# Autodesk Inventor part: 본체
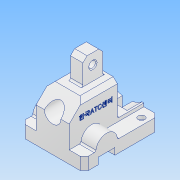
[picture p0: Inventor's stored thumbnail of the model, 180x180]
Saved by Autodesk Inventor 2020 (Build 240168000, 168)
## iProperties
Created: 2022-08
Part Number: 본체
Material: 알루미늄 6061
Document SubType Name: Modeling
Designer: user
Density: 2.7 g/cm^3
Appearance: 알루미늄 - 평지
Mass: 498.899 g
Surface Area: 338.01 cm^2
Volume: 184.777 cm^3
Author: user
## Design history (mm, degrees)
sketch "스케치1"
  geometry: L1 (20, -22.5)-(-20, -22.5); L2 (-20, -22.5)-(-20, 22.5); L3 (-20, 22.5)-(20, 22.5); L4 (20, 22.5)-(20, -22.5); L5 (20, -22.5)-(-20, 22.5); L6 (-20, -22.5)-(20, 22.5); 1 further point
  constraints: 12 end point, 2 midpoint, 2 parallel, 1 horizontal, 1 perpendicular
  dimensions: "d0" = 45 distance of L1.end L2.end; "d1" = 40 distance of L2.end L3.end
extrude "돌출1" new body sketch "스케치1" distance "d2" = 58; taper "d3" = 0 deg
chamfer "모따기1" distance "d4" = 18; stored, may be unused: second distance "d5" = 2, angle "d6" = 45 deg
chamfer "모따기2" distance "d7" = 5; stored, may be unused: second distance "d8" = 2, angle "d9" = 45 deg
sketch "스케치2"
  geometry: L1 (20, -22.5)-(-20, -22.5) reference; L2 (-15, 22.5)-(15, 22.5) reference; C1 r 10 at (0, 4.5); 1 further point
  constraints: 1 centre point, 1 midpoint, 1 vertical alignment
  dimensions: "d10" = 20 diameter of C1; "d57" = 27 distance from line of L1 C1.centre
extrude "돌출2" cut sketch "스케치2" extent not by distance; stored distance "d11" = 0; taper "d12" = 0 deg
sketch "스케치3"
  geometry: L1 (-20, -22.5)-(20, -22.5) reference; L2 (15, 22.5)-(-15, 22.5) reference; C1 r 14.5 at (0, 4.5); 1 further point
  constraints: 1 centre point, 1 midpoint, 1 vertical alignment
  dimensions: "d13" = 29 diameter of C1; "d58" = 27 distance from line of L1 C1.centre
extrude "돌출3" cut sketch "스케치3" distance "d14" = 7; taper "d15" = 0 deg
sketch "스케치4"
  geometry: L1 (7.5, 11)-(22.5, 11); L2 (22.5, 11)-(22.5, 35); L3 (22.5, 35)-(7.5, 35); L4 (7.5, 35)-(7.5, 11); L5 (0, 40)-(30, 40) reference; 2 further points
  constraints: 8 end point, 2 parallel, 1 horizontal, 1 midpoint, 1 perpendicular, 1 vertical alignment
  dimensions: "d16" = 24 distance of L3.end L1.start; "d17" = 5 distance between parallel lines of L5 L3; "d18" = 15 distance of L1.start L1.end
extrude "돌출4" join sketch "스케치4" distance "d19" = 30; taper "d20" = 0 deg
chamfer "모따기3" distance "d21" = 5; stored, may be unused: second distance "d22" = 2, angle "d23" = 45 deg
sketch "스케치5"
  geometry: L1 (24, 0)-(24, 25) reference; L2 (22, -3.5)-(22, -32.5) reference; L3 (29, -3.5)-(29, -32.5) reference; L4 (29, -45)-(29, -5) reference; L5 (29, -18)-(22, -18); L6 (22, -28)-(22, -8) reference; L7 (19, 30)-(5, 30) reference; C1 r 4 at (12, 17); 2 further points
  constraints: 2 end point, 2 midpoint, 1 centre point, 1 horizontal, 1 point on line, 1 vertical alignment
  dimensions: "d60" = 8 diameter of C1; "d61" = 35 vertical distance of L5.start C1.centre
extrude "돌출5" cut sketch "스케치5" extent not by distance; stored distance "d27" = 0; taper "d28" = 0 deg
sketch "스케치6"
  geometry: L1 (0, 0)-(0, 27) reference; L2 (0, 0)-(90, 0); L3 (90, 0)-(90, -15); L4 (90, -15)-(0, -15); L5 (0, -15)-(0, 0); L6 (0, 0)-(58, 0) reference; L7 (17, -15)-(37, -15); L8 (37, -15)-(37, -7); L9 (37, -7)-(17, -7); L10 (17, -7)-(17, -15); A1 r 13 centre (27, 0) between (40, 0) and (14, 0); 5 further points
  constraints: 16 end point, 4 parallel, 4 point on line, 2 horizontal, 2 perpendicular, 2 point on circle, 1 centre point, 1 midpoint, 1 vertical alignment
  dimensions: "d37" = 90 distance of L3.end L4.end; "d38" = 15 distance of L4.end L1.start; "d39" = 26 diameter of A1; "d40" = 27 distance from line of A1.centre L5; "d41" = 8 distance between parallel lines of L4 L9; "d42" = 20 distance of L8.end L9.end
extrude "돌출6" join sketch "스케치6" distance "d43" = 18; taper "d44" = 0 deg
sketch "스케치7"
  geometry: L1 (0, 0)-(-18, 0) reference; L2 (40, 15)-(40, 0) reference; L3 (0, 0)-(40, 0); L4 (40, 0)-(40, 15); L5 (40, 15)-(0, 15); L6 (0, 15)-(0, 0); 2 further points
  constraints: 8 end point, 2 parallel, 1 horizontal, 1 perpendicular
extrude "돌출7" join sketch "스케치7" distance "d45" = 90; taper "d46" = 0 deg
sketch "스케치8"
  geometry: L1 (-22.5, -40)-(-22.5, -58) reference; L2 (-22.5, -58)-(-18.5, -58); L3 (-18.5, -58)-(-18.5, -90); L4 (-18.5, -90)-(-22.5, -90); L5 (-22.5, -90)-(-22.5, -58); L6 (-37.5, -37)-(-37.5, -90) reference; 2 further points
  constraints: 8 end point, 2 parallel, 1 coincident, 1 horizontal, 1 perpendicular
  dimensions: "d47" = 19 distance between parallel lines of L6 L3
extrude "돌출8" join sketch "스케치8" stored distance "d48" = 40; taper "d49" = 0 deg
sketch "스케치9"
  geometry: C1 r 29 at (38, 27); C2 r 14.5 at (38, 27) reference
  constraints: 1 centre point, 1 coincident
  dimensions: "d84" = 58 diameter of C1
extrude "돌출9" cut sketch "스케치9" distance "d51" = 18; taper "d52" = 0 deg
sketch "스케치10"
  geometry: L1 (76, -15)-(0, -15) reference; L2 (32, -15)-(44, -15); L3 (44, -15)-(44, 4); L4 (44, 4)-(32, 4); L5 (32, 4)-(32, -15); 3 further points
  constraints: 8 end point, 2 parallel, 1 horizontal, 1 midpoint, 1 perpendicular, 1 point on line, 1 vertical alignment
  dimensions: "d53" = 12 distance of L3.end L4.end; "d54" = 19 distance of L4.end L2.start
extrude "돌출10" cut sketch "스케치10" distance "d55" = 18; taper "d56" = 0 deg
sketch "스케치11"
  geometry: L1 (-14, 50)-(18, 50) reference; 3 further points
  constraints: 1 horizontal alignment
  dimensions: "d62" = 60 distance of point (10, 37) point (-50, 37); "d63" = 30 horizontal distance of point (-20, -40) point (-50, 37); "d64" = 13 distance from line of L1 point (10, 37)
hole "구멍1" sketch "스케치11" at (-50, 37), (10, 37) diameter "d65" = 4.5; stored, may be unused: countersink angle "d69" = 90 deg, drill point angle "d71" = 0 deg; dims "d66" = 10, "d67" = 8, "d68" = 4.4, "d70" = 12
chamfer "모따기4" distance "d72" = 5; stored, may be unused: second distance "d73" = 2, angle "d74" = 45 deg
fillet "모깎기1" dims "d75" = 2
node "작업 평면1"
sketch "스케치12"
  geometry: L1 (45, 5)-(5, 5) reference; L2 (45, 0)-(45, -34) reference; 2 further points
  constraints: 1 other
  dimensions: "d77" = 18 distance from line of point (19, -13) L1; "d78" = 26 distance from line of L2 point (19, -13)
feature "엠보싱1" sketch "스케치12" dims "d0" = 45, "d1" = 40, "d79" = 0.5, "d80" = 0
chamfer "모따기5" distance "d81" = 1; stored, may be unused: second distance "d82" = 2, angle "d83" = 45 deg
sketch "스케치13"
  geometry: L1 (-20, 8)-(0, 8) reference; L2 (0, 0)-(48, 0) reference; L3 (-20, 8)-(0, 8); L4 (0, 8)-(0, 0); L5 (0, 0)-(-20, 0); L6 (-20, 0)-(-20, 8); 2 further points
  constraints: 8 end point, 2 parallel, 1 horizontal, 1 perpendicular
extrude "돌출11" cut sketch "스케치13" extent not by distance; stored distance "d85" = 18; taper "d86" = 0 deg
node "솔리드1"
mirror "미러1"
node "투영된 루프1"
feature "A9D066F2-1C7D-4E18-AEED-F7BC21143FA4" dims "d65" = 4.5, "d66" = 10, "d67" = 8, "d68" = 4.4, "d69" = 90 deg, "d70" = 12, "d71" = 0
other parameters: "d32" = 8, "d76" = 22.75
